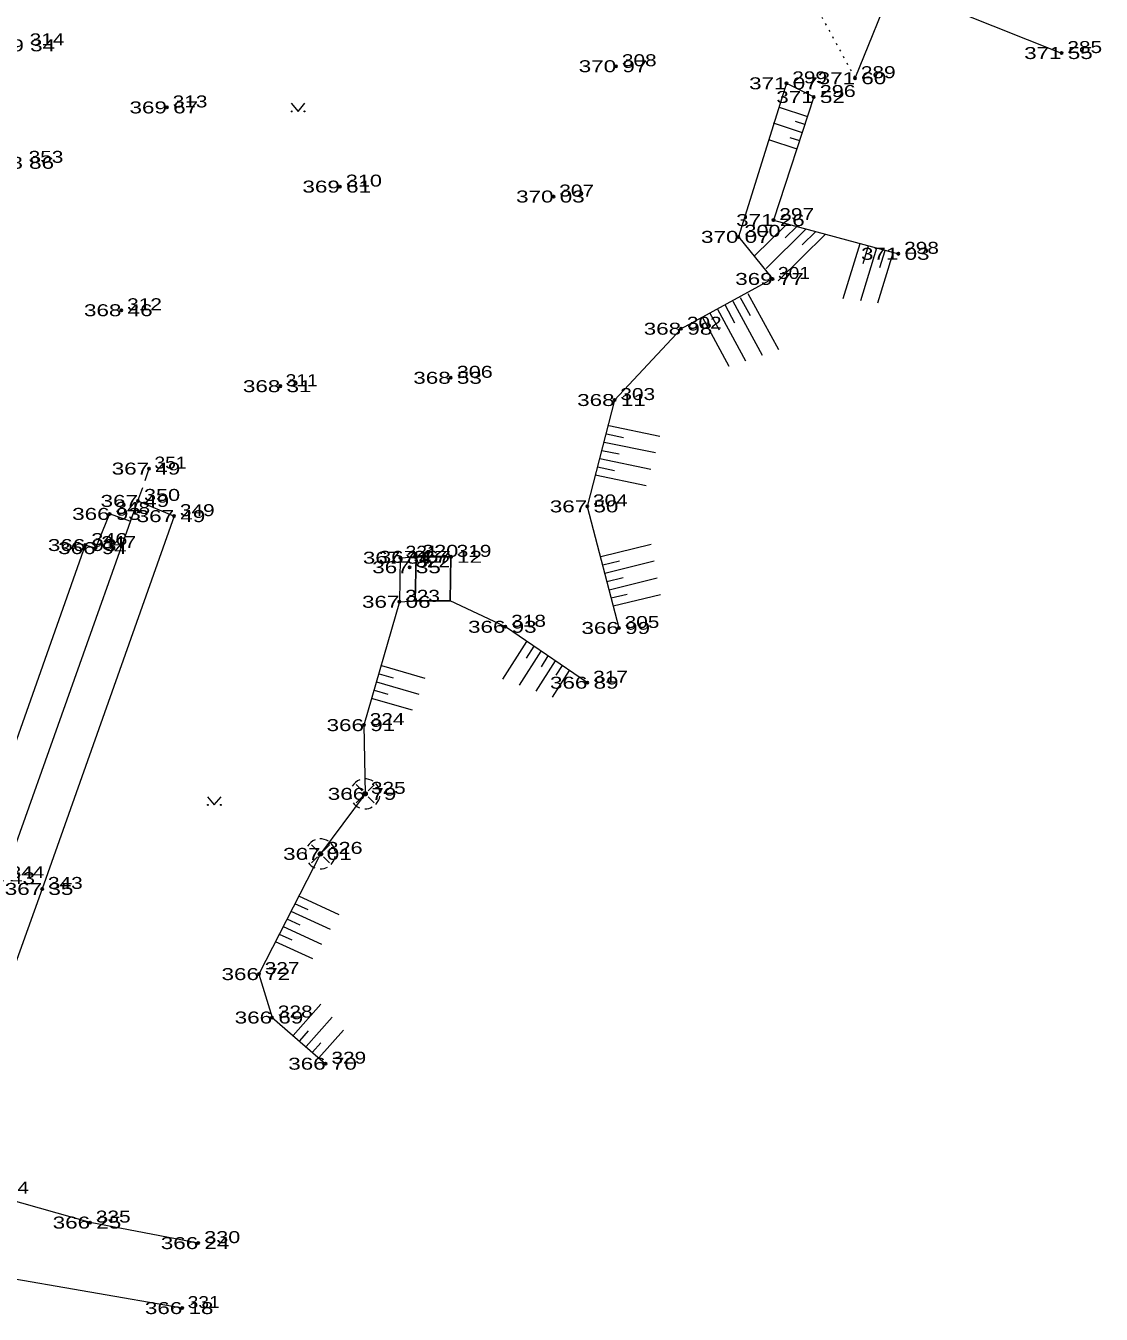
# Model space of a CAD drawing. Extents: x -789669 to -789458, y -977587 to -977420.
# Drawn here: x -789529.3 to -789466.4, y -977586.7 to -977511.4 of the extents above; entities that cross this region are included whole.
import ezdxf
from ezdxf.enums import TextEntityAlignment as Align

# ---------------------------------------------------------------- set-up
doc = ezdxf.new("R2010")
doc.units = 0
doc.header["$LTSCALE"] = 0.28
doc.header["$PDMODE"] = 32
doc.header["$PDSIZE"] = 0.14
doc.linetypes.add('DOTTED', pattern=[1.5, 0.3, -1.2])
doc.linetypes.add('MEDIUM_DASHED', pattern=[4.5, 3, -1.5])
for name, color, linetype, lineweight in [('1', 7, 'Continuous', 13), ('2', 7, 'Continuous', 13), ('4', 7, 'Continuous', 13), ('9', 7, 'Continuous', 25)]:
    doc.layers.add(name, color=color, linetype=linetype, lineweight=lineweight)
for name, color, linetype in [('57', 7, 'Continuous'), ('58', 7, 'Continuous'), ('59', 7, 'Continuous')]:
    doc.layers.add(name, color=color, linetype=linetype)

msp = doc.modelspace()

# ---------------------------------------------------------------- linework, layer by layer
at = {"layer": '1', "linetype": 'DOTTED'}
msp.add_line((-789482.95, -977510.48), (-789480.79, -977514.44), dxfattribs=at)
at = {"layer": '1', "linetype": 'MEDIUM_DASHED'}
msp.add_line((-789522.71, -977539.16), (-789522.06, -977537.27), dxfattribs=at)
at = {"layer": '1'}
for p, q in [((-789523.136, -977540.359), (-789524.37, -977539.92)), ((-789507.38, -977542.48), (-789507.43, -977545.06)), ((-789507.38, -977542.48), (-789506.45, -977542.43)), ((-789507.43, -977545.06), (-789506.5, -977545.01)), ((-789520.12, -977586.36), (-789532.99, -977584.13))]:
    msp.add_line(p, q, dxfattribs=at)
for points in [[(-789480.79, -977514.44), (-789478.42, -977508.61), (-789474.64, -977510.14), (-789474.64, -977510.14), (-789474.75, -977510.58), (-789468.72, -977512.97)], [(-789524.37, -977539.92), (-789525.19, -977541.92), (-789525.79, -977541.74), (-789532.44, -977560.54), (-789537.78, -977574.98)], [(-789519.19, -977582.56), (-789525.51, -977581.36), (-789531.45, -977579.67)]]:
    msp.add_lwpolyline(points, dxfattribs=at)
msp.add_lwpolyline([(-789522.71, -977539.16), (-789520.6, -977540.05), (-789528.31, -977561.85), (-789533.56, -977576.42), (-789535.63, -977575.89), (-789530.55, -977561.22)], close=True, dxfattribs=at)
at = {"layer": '2'}
for p, q in [((-789484.8, -977514.74), (-789487.61, -977523.72)), ((-789485.235, -977516.13), (-789483.577, -977516.672)), ((-789483.874, -977517.627), (-789485.567, -977517.074)), ((-789483.725, -977517.15), (-789484.283, -977516.967)), ((-789484.171, -977518.582), (-789485.832, -977518.039)), ((-789484.022, -977518.105), (-789484.588, -977517.92)), ((-789486.692, -977524.85), (-789484.761, -977522.956)), ((-789484.201, -977523.107), (-789484.885, -977523.778)), ((-789483.641, -977523.258), (-789485.994, -977525.566)), ((-789482.521, -977523.56), (-789485.296, -977526.282)), ((-789483.081, -977523.409), (-789483.877, -977524.19)), ((-789481.48, -977527.32), (-789480.499, -977524.106)), ((-789479.54, -977524.389), (-789480.478, -977527.461)), ((-789480.019, -977524.247), (-789480.34, -977525.297)), ((-789479.06, -977524.53), (-789479.367, -977525.535)), ((-789478.58, -977524.671), (-789479.475, -977527.603)), ((-789487.947, -977527.487), (-789486.229, -977530.634)), ((-789487.504, -977527.255), (-789486.921, -977528.323)), ((-789487.061, -977527.023), (-789485.269, -977530.304)), ((-789488.147, -977531.294), (-789489.719, -977528.415)), ((-789489.276, -977528.183), (-789488.74, -977529.164)), ((-789488.833, -977527.951), (-789487.188, -977530.964)), ((-789488.39, -977527.719), (-789487.831, -977528.743)), ((-789495.193, -977534.753), (-789492.197, -977535.371)), ((-789495.455, -977535.72), (-789492.464, -977536.337)), ((-789495.324, -977535.237), (-789494.326, -977535.442)), ((-789495.718, -977536.687), (-789492.731, -977537.303)), ((-789495.586, -977536.204), (-789494.59, -977536.409)), ((-789495.849, -977537.171), (-789494.854, -977537.376)), ((-789492.998, -977538.269), (-789495.98, -977537.654)), ((-789495.661, -977542.412), (-789492.718, -977541.687)), ((-789495.539, -977542.897), (-789494.572, -977542.659)), ((-789495.418, -977543.382), (-789492.536, -977542.672)), ((-789495.296, -977543.867), (-789494.348, -977543.634)), ((-789495.174, -977544.352), (-789492.355, -977543.658)), ((-789495.052, -977544.837), (-789494.123, -977544.608)), ((-789492.174, -977544.643), (-789494.93, -977545.322)), ((-789501.23, -977546.52), (-789504.47, -977545.01)), ((-789496.44, -977549.79), (-789501.23, -977546.52)), ((-789501.388, -977549.592), (-789499.983, -977547.372)), ((-789499.157, -977547.937), (-789500.424, -977549.939)), ((-789499.57, -977547.654), (-789500.017, -977548.361)), ((-789498.331, -977548.502), (-789499.461, -977550.287)), ((-789498.744, -977548.219), (-789499.148, -977548.858)), ((-789508.619, -977549.27), (-789507.793, -977549.507)), ((-789508.475, -977548.791), (-789505.934, -977549.522)), ((-789497.505, -977549.067), (-789498.497, -977550.634)), ((-789497.918, -977548.784), (-789498.28, -977549.356)), ((-789508.907, -977550.227), (-789508.102, -977550.459)), ((-789508.763, -977549.748), (-789506.302, -977550.457)), ((-789506.669, -977551.392), (-789509.051, -977550.706)), ((-789513.333, -977562.256), (-789510.966, -977563.341)), ((-789513.556, -977562.704), (-789512.782, -977563.059)), ((-789514.003, -977563.599), (-789513.248, -977563.945)), ((-789513.78, -977563.151), (-789511.475, -977564.207)), ((-789514.45, -977564.494), (-789513.714, -977564.831)), ((-789514.226, -977564.047), (-789511.985, -977565.074)), ((-789512.495, -977565.94), (-789514.673, -977564.942)), ((-789513.633, -977570.412), (-789512.026, -977568.583)), ((-789512.882, -977571.072), (-789511.361, -977569.342)), ((-789513.258, -977570.742), (-789512.738, -977570.151)), ((-789510.697, -977570.101), (-789512.131, -977571.732)), ((-789512.507, -977571.402), (-789512.015, -977570.843))]:
    msp.add_line(p, q, dxfattribs=at)
for points in [[(-789484.8, -977514.74), (-789483.21, -977515.54), (-789485.56, -977522.74), (-789478.26, -977524.71)], [(-789487.61, -977523.72), (-789485.61, -977526.18), (-789490.96, -977529.09), (-789494.85, -977533.26), (-789496.45, -977539.48), (-789494.6, -977546.59)], [(-789507.43, -977545.06), (-789509.5, -977552.27), (-789509.43, -977556.29), (-789512.04, -977559.8), (-789515.64, -977566.83), (-789514.87, -977569.37), (-789511.74, -977572.07)]]:
    msp.add_lwpolyline(points, dxfattribs=at)
at = {"layer": '4'}
for p, q in [((-789509.964, -977555.752), (-789509.607, -977556.108)), ((-789509.43, -977556.296), (-789509.43, -977556.284)), ((-789508.904, -977555.76), (-789509.257, -977556.113)), ((-789509.96, -977556.823), (-789509.608, -977556.472)), ((-789509.256, -977556.467), (-789508.904, -977556.817)), ((-789512.574, -977559.262), (-789512.217, -977559.618)), ((-789511.514, -977559.27), (-789511.867, -977559.623)), ((-789512.57, -977560.333), (-789512.218, -977559.982)), ((-789512.04, -977559.806), (-789512.04, -977559.794)), ((-789511.866, -977559.977), (-789511.514, -977560.327))]:
    msp.add_line(p, q, dxfattribs=at)
for points in [[(-789513.753, -977515.902), (-789513.351, -977516.381), (-789512.949, -977515.902)], [(-789513.725, -977516.358), (-789513.711, -977516.366), (-789513.706, -977516.381), (-789513.712, -977516.394), (-789513.725, -977516.402), (-789513.741, -977516.394), (-789513.747, -977516.381), (-789513.743, -977516.367), (-789513.732, -977516.361), (-789513.717, -977516.367), (-789513.712, -977516.381), (-789513.715, -977516.391), (-789513.725, -977516.396), (-789513.736, -977516.391), (-789513.742, -977516.38), (-789513.737, -977516.37), (-789513.732, -977516.367), (-789513.721, -977516.371), (-789513.716, -977516.381), (-789513.722, -977516.388), (-789513.73, -977516.386), (-789513.735, -977516.378), (-789513.73, -977516.373), (-789513.722, -977516.377), (-789513.725, -977516.381)], [(-789512.975, -977516.359), (-789512.961, -977516.367), (-789512.956, -977516.382), (-789512.962, -977516.395), (-789512.975, -977516.403), (-789512.991, -977516.395), (-789512.997, -977516.382), (-789512.993, -977516.368), (-789512.982, -977516.362), (-789512.967, -977516.368), (-789512.962, -977516.382), (-789512.965, -977516.392), (-789512.975, -977516.397), (-789512.986, -977516.392), (-789512.992, -977516.381), (-789512.987, -977516.371), (-789512.982, -977516.368), (-789512.971, -977516.372), (-789512.966, -977516.382), (-789512.972, -977516.389), (-789512.98, -977516.387), (-789512.985, -977516.379), (-789512.98, -977516.374), (-789512.972, -977516.378), (-789512.975, -977516.382)], [(-789518.651, -977556.459), (-789518.249, -977556.938), (-789517.847, -977556.459)], [(-789518.623, -977556.915), (-789518.609, -977556.923), (-789518.604, -977556.938), (-789518.61, -977556.951), (-789518.623, -977556.959), (-789518.639, -977556.951), (-789518.645, -977556.938), (-789518.641, -977556.924), (-789518.63, -977556.918), (-789518.615, -977556.924), (-789518.61, -977556.938), (-789518.613, -977556.948), (-789518.623, -977556.953), (-789518.634, -977556.948), (-789518.64, -977556.937), (-789518.635, -977556.927), (-789518.63, -977556.924), (-789518.619, -977556.928), (-789518.614, -977556.938), (-789518.62, -977556.945), (-789518.628, -977556.943), (-789518.633, -977556.935), (-789518.628, -977556.93), (-789518.62, -977556.934), (-789518.623, -977556.938)], [(-789517.873, -977556.916), (-789517.859, -977556.924), (-789517.854, -977556.939), (-789517.86, -977556.952), (-789517.873, -977556.96), (-789517.889, -977556.952), (-789517.895, -977556.939), (-789517.891, -977556.925), (-789517.88, -977556.919), (-789517.865, -977556.925), (-789517.86, -977556.939), (-789517.863, -977556.949), (-789517.873, -977556.954), (-789517.884, -977556.949), (-789517.89, -977556.938), (-789517.885, -977556.928), (-789517.88, -977556.925), (-789517.869, -977556.929), (-789517.864, -977556.939), (-789517.87, -977556.946), (-789517.878, -977556.944), (-789517.883, -977556.936), (-789517.878, -977556.931), (-789517.87, -977556.935), (-789517.873, -977556.939)]]:
    msp.add_lwpolyline(points, dxfattribs=at)
for centre, radius in [((-789513.726, -977516.381), 0.025), ((-789512.976, -977516.381), 0.025), ((-789509.4339, -977556.2894), 0.125), ((-789518.624, -977556.938), 0.025), ((-789517.874, -977556.938), 0.025), ((-789512.0439, -977559.7994), 0.125)]:
    msp.add_circle(centre, radius, dxfattribs=at)
for centre, start, end in [((-789509.4339, -977556.2894), 111.04924, 149.34666), ((-789509.4339, -977556.2894), 57.94289, 92.85253), ((-789509.4339, -977556.2894), 166.76695, 200.11735), ((-789509.4339, -977556.2894), 9.68453, 44.47714), ((-789509.4339, -977556.2894), 217.06959, 247.69959), ((-789509.4339, -977556.2894), 315.09105, 351.67435), ((-789509.4339, -977556.2894), 269.18965, 298.56841), ((-789512.0439, -977559.7994), 111.04924, 149.34666), ((-789512.0439, -977559.7994), 57.94289, 92.85253), ((-789512.0439, -977559.7994), 9.68453, 44.47714), ((-789512.0439, -977559.7994), 166.76695, 200.11735), ((-789512.0439, -977559.7994), 315.09105, 351.67435), ((-789512.0439, -977559.7994), 217.06959, 247.69959), ((-789512.0439, -977559.7994), 269.18965, 298.56841)]:
    msp.add_arc(centre, 0.875, start, end, dxfattribs=at)
at = {"layer": '57'}
for p in [(-789468.72, -977512.97), (-789494.76, -977513.74), (-789484.8, -977514.74), (-789480.79, -977514.44), (-789483.21, -977515.54), (-789521.02, -977516.15), (-789510.91, -977520.78), (-789498.42, -977521.36), (-789485.56, -977522.74), (-789487.61, -977523.72), (-789478.26, -977524.71), (-789485.61, -977526.18), (-789523.68, -977528.01), (-789490.96, -977529.09), (-789504.43, -977531.96), (-789514.39, -977532.45), (-789494.85, -977533.26), (-789522.06, -977537.27), (-789522.71, -977539.16), (-789496.45, -977539.48), (-789524.37, -977539.92), (-789520.6, -977540.05), (-789525.79, -977541.74), (-789525.19, -977541.92), (-789507.38, -977542.48), (-789506.45, -977542.43), (-789504.42, -977542.43), (-789506.83, -977543.04), (-789507.43, -977545.06), (-789501.23, -977546.52), (-789494.6, -977546.59), (-789496.44, -977549.79), (-789509.5, -977552.27), (-789509.43, -977556.29), (-789512.04, -977559.8), (-789528.31, -977561.85), (-789515.64, -977566.83), (-789514.87, -977569.37), (-789511.74, -977572.07), (-789525.51, -977581.36), (-789519.19, -977582.56), (-789520.12, -977586.36)]:
    msp.add_point(p, dxfattribs=at)
at = {"layer": '9'}
for p in [(-789504.42, -977542.43), (-789506.5, -977545.01)]:
    msp.add_line(p, (-789504.47, -977545.01), dxfattribs=at)
msp.add_lwpolyline([(-789504.42, -977542.43), (-789506.45, -977542.43), (-789506.5, -977545.01)], dxfattribs=at)

# ---------------------------------------------------------------- texts
at = {"layer": '58'}
for s, width, p in [(' 314', 1.3, (-789529.38, -977512.52)), (' 285', 1.3, (-789468.72, -977512.97)), (' 308', 1.3, (-789494.76, -977513.74)), (' 299', 1.3, (-789484.8, -977514.74)), (' 289', 1.3, (-789480.79, -977514.44)), (' 296', 1.35, (-789483.21, -977515.54)), (' 313', 1.3, (-789521.02, -977516.15)), (' 353', 1.3, (-789529.44, -977519.39)), (' 310', 1.35, (-789510.91, -977520.78)), (' 307', 1.3, (-789498.42, -977521.36)), (' 297', 1.3, (-789485.56, -977522.74)), (' 300', 1.35, (-789487.61, -977523.72)), (' 298', 1.3, (-789478.26, -977524.71)), (' 301', 1.2, (-789485.61, -977526.18)), (' 312', 1.3, (-789523.68, -977528.01)), (' 302', 1.3, (-789490.96, -977529.09)), (' 306', 1.35, (-789504.43, -977531.96)), (' 311', 1.2, (-789514.39, -977532.45)), (' 303', 1.3, (-789494.85, -977533.26)), (' 351', 1.2, (-789522.06, -977537.27)), (' 350', 1.35, (-789522.71, -977539.16)), (' 304', 1.3, (-789496.45, -977539.48)), (' 348', 1.3, (-789524.37, -977539.92)), (' 349', 1.3, (-789520.6, -977540.05)), (' 346', 1.35, (-789525.79, -977541.74)), (' 347', 1.3, (-789525.19, -977541.92)), (' 321', 1.2, (-789507.38, -977542.48)), (' 320', 1.35, (-789506.45, -977542.43)), (' 319', 1.3, (-789504.42, -977542.43)), (' 322', 1.3, (-789506.83, -977543.04)), (' 323', 1.3, (-789507.43, -977545.06)), (' 318', 1.3, (-789501.23, -977546.52)), (' 305', 1.3, (-789494.6, -977546.59)), (' 317', 1.3, (-789496.44, -977549.79)), (' 324', 1.3, (-789509.5, -977552.27)), (' 325', 1.3, (-789509.43, -977556.29)), (' 326', 1.35, (-789512.04, -977559.8)), (' 344', 1.3, (-789530.55, -977561.22)), (' 343', 1.3, (-789528.31, -977561.85)), (' 327', 1.3, (-789515.64, -977566.83)), (' 328', 1.3, (-789514.87, -977569.37)), (' 329', 1.3, (-789511.74, -977572.07)), (' 334', 1.3, (-789531.45, -977579.67)), (' 335', 1.3, (-789525.51, -977581.36)), (' 330', 1.35, (-789519.19, -977582.56)), (' 331', 1.2, (-789520.12, -977586.36))]:
    msp.add_text(s, height=0.7, dxfattribs=dict(at, width=width)).set_placement(p)
at = {"layer": '59', "width": 1.4}
for s, p in [('369 34 ', (-789529.38, -977512.87)), ('371 55 ', (-789468.72, -977513.32)), ('370 97 ', (-789494.76, -977514.09)), ('371 60 ', (-789480.79, -977514.79)), ('371 07 ', (-789484.8, -977515.09)), ('371 52 ', (-789483.21, -977515.89)), ('369 67 ', (-789521.02, -977516.5)), ('368 86 ', (-789529.44, -977519.74)), ('369 61 ', (-789510.91, -977521.13)), ('370 03 ', (-789498.42, -977521.71)), ('371 26 ', (-789485.56, -977523.09)), ('370 07 ', (-789487.61, -977524.07)), ('371 03 ', (-789478.26, -977525.06)), ('369 77 ', (-789485.61, -977526.53)), ('368 46 ', (-789523.68, -977528.36)), ('368 98 ', (-789490.96, -977529.44)), ('368 31 ', (-789514.39, -977532.8)), ('368 53 ', (-789504.43, -977532.31)), ('368 11 ', (-789494.85, -977533.61)), ('367 49 ', (-789522.06, -977537.62)), ('367 49 ', (-789522.71, -977539.51)), ('366 93 ', (-789524.37, -977540.27)), ('367 49 ', (-789520.6, -977540.4)), ('367 50 ', (-789496.45, -977539.83)), ('366 93 ', (-789525.79, -977542.09)), ('366 94 ', (-789525.19, -977542.27)), ('367 34 ', (-789507.38, -977542.83)), ('367 35 ', (-789506.83, -977543.39)), ('367 27 ', (-789506.45, -977542.78)), ('367 12 ', (-789504.42, -977542.78)), ('367 06 ', (-789507.43, -977545.41)), ('366 93 ', (-789501.23, -977546.87)), ('366 99 ', (-789494.6, -977546.94)), ('366 89 ', (-789496.44, -977550.14)), ('366 91 ', (-789509.5, -977552.62)), ('366 79 ', (-789509.43, -977556.64)), ('367 01 ', (-789512.04, -977560.15)), ('367 43 ', (-789530.55, -977561.57)), ('367 35 ', (-789528.31, -977562.2)), ('366 72 ', (-789515.64, -977567.18)), ('366 69 ', (-789514.87, -977569.72)), ('366 70 ', (-789511.74, -977572.42)), ('366 25 ', (-789525.51, -977581.71)), ('366 24 ', (-789519.19, -977582.91)), ('366 18 ', (-789520.12, -977586.71))]:
    msp.add_text(s, height=0.7, dxfattribs=at).set_placement(p, align=Align.CENTER)

doc.saveas('drawing.dxf')
